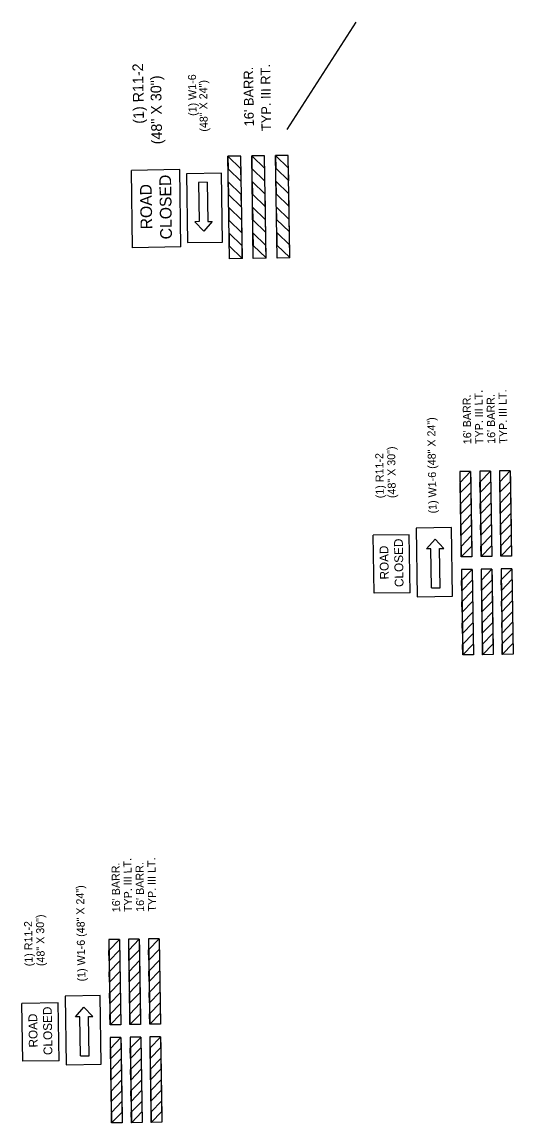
# Model space of a CAD drawing. Extents: x 1770018 to 1773492, y 718230 to 729141.
# Drawn here: x 1773099 to 1773468, y 718477 to 719302 of the extents above; entities that cross this region are included whole.
import ezdxf

# ---------------------------------------------------------------- set-up
doc = ezdxf.new("R2010")
doc.units = 0
doc.layers.add('R_Border PE', color=7, linetype='Continuous')
doc.layers.add('R_MOT', color=7, linetype='Continuous')

msp = doc.modelspace()

# ---------------------------------------------------------------- linework, layer by layer
at = {"layer": 'R_Border PE'}
msp.add_line((1773298.17, 719221.46), (1773350.06, 719301.98), dxfattribs=at)
at = {"layer": 'R_MOT'}
for p, q in [((1773263.38, 719201.45), (1773253.73, 719201.3)), ((1773254.92, 719124.43), (1773253.73, 719201.3)), ((1773263.36, 719201.39), (1773263.3, 719201.45)), ((1773264.57, 719124.58), (1773263.38, 719201.45)), ((1773281.25, 719201.72), (1773271.62, 719201.58)), ((1773281.25, 719201.72), (1773271.62, 719201.58)), ((1773272.81, 719124.71), (1773271.62, 719201.58)), ((1773282.43, 719124.86), (1773281.25, 719201.72)), ((1773299.08, 719202), (1773289.46, 719201.85)), ((1773290.64, 719124.98), (1773289.46, 719201.85)), ((1773300.26, 719125.13), (1773299.08, 719202)), ((1773217.53, 719191.29), (1773181.32, 719190.73)), ((1773182.22, 719132.77), (1773181.32, 719190.73)), ((1773218.42, 719133.33), (1773217.53, 719191.29)), ((1773238.26, 719181.82), (1773231.72, 719181.72)), ((1773231.72, 719181.72), (1773232.17, 719152.33)), ((1773238.26, 719181.82), (1773238.72, 719152.43)), ((1773232.17, 719152.33), (1773228.9, 719152.28)), ((1773235.55, 719145.21), (1773228.9, 719152.28)), ((1773241.99, 719152.48), (1773235.55, 719145.21)), ((1773238.72, 719152.43), (1773241.99, 719152.48)), ((1773218.42, 719133.33), (1773182.22, 719132.77)), ((1773264.57, 719124.58), (1773254.92, 719124.43)), ((1773282.43, 719124.86), (1773272.81, 719124.71)), ((1773300.26, 719125.13), (1773290.64, 719124.98)), ((1773435.89, 718965.08), (1773427.85, 718964.95)), ((1773427.85, 718964.95), (1773428.84, 718900.93)), ((1773435.89, 718965.08), (1773436.87, 718901.05)), ((1773450.77, 718965.3), (1773442.75, 718965.18)), ((1773442.75, 718965.18), (1773443.74, 718901.16)), ((1773450.77, 718965.3), (1773451.75, 718901.28)), ((1773465.62, 718965.53), (1773457.61, 718965.41)), ((1773457.61, 718965.41), (1773458.59, 718901.39)), ((1773465.62, 718965.53), (1773466.61, 718901.51)), ((1773389.88, 718917.52), (1773362.74, 718917.11)), ((1773363.41, 718873.66), (1773362.74, 718917.11)), ((1773390.55, 718874.08), (1773389.88, 718917.52)), ((1773402.84, 718907.06), (1773409.27, 718914.33)), ((1773409.27, 718914.33), (1773415.93, 718907.26)), ((1773406.11, 718907.11), (1773402.84, 718907.06)), ((1773406.56, 718877.72), (1773406.11, 718907.11)), ((1773412.65, 718907.21), (1773415.93, 718907.26)), ((1773413.11, 718877.82), (1773412.65, 718907.21)), ((1773436.87, 718901.05), (1773428.84, 718900.93)), ((1773436.85, 718901.1), (1773436.8, 718901.05)), ((1773451.75, 718901.28), (1773443.74, 718901.16)), ((1773451.75, 718901.28), (1773443.74, 718901.16)), ((1773466.61, 718901.51), (1773458.59, 718901.39)), ((1773437.02, 718891.55), (1773428.98, 718891.43)), ((1773428.98, 718891.43), (1773429.97, 718827.41)), ((1773437.02, 718891.55), (1773438.01, 718827.53)), ((1773451.9, 718891.78), (1773443.88, 718891.66)), ((1773443.88, 718891.66), (1773444.87, 718827.63)), ((1773451.9, 718891.78), (1773452.89, 718827.76)), ((1773466.75, 718892.01), (1773458.74, 718891.89)), ((1773458.74, 718891.89), (1773459.72, 718827.86)), ((1773466.75, 718892.01), (1773467.74, 718827.99)), ((1773390.55, 718874.08), (1773363.41, 718873.66)), ((1773406.56, 718877.72), (1773413.11, 718877.82)), ((1773438.01, 718827.53), (1773429.97, 718827.41)), ((1773437.98, 718827.58), (1773437.94, 718827.53)), ((1773452.89, 718827.76), (1773444.87, 718827.63)), ((1773452.89, 718827.76), (1773444.87, 718827.63)), ((1773467.74, 718827.99), (1773459.72, 718827.86)), ((1773172.33, 718614.17), (1773164.29, 718614.05)), ((1773164.29, 718614.05), (1773165.27, 718550.03)), ((1773172.33, 718614.17), (1773173.31, 718550.15)), ((1773187.21, 718614.4), (1773179.19, 718614.28)), ((1773179.19, 718614.28), (1773180.18, 718550.26)), ((1773187.21, 718614.4), (1773188.19, 718550.38)), ((1773202.06, 718614.63), (1773194.04, 718614.51)), ((1773194.04, 718614.51), (1773195.03, 718550.48)), ((1773202.06, 718614.63), (1773203.05, 718550.61)), ((1773126.32, 718566.62), (1773099.18, 718566.21)), ((1773099.85, 718522.76), (1773099.18, 718566.21)), ((1773126.99, 718523.18), (1773126.32, 718566.62)), ((1773139.28, 718556.15), (1773145.71, 718563.43)), ((1773145.71, 718563.43), (1773152.37, 718556.36)), ((1773142.55, 718556.2), (1773139.28, 718556.15)), ((1773143, 718526.82), (1773142.55, 718556.2)), ((1773149.09, 718556.31), (1773152.37, 718556.36)), ((1773149.55, 718526.92), (1773149.09, 718556.31)), ((1773188.19, 718550.38), (1773180.18, 718550.26)), ((1773188.19, 718550.38), (1773180.18, 718550.26)), ((1773203.05, 718550.61), (1773195.03, 718550.48)), ((1773173.31, 718550.15), (1773165.27, 718550.03)), ((1773173.29, 718550.2), (1773173.24, 718550.15)), ((1773173.46, 718540.65), (1773165.42, 718540.53)), ((1773165.42, 718540.53), (1773166.41, 718476.5)), ((1773173.46, 718540.65), (1773174.45, 718476.63)), ((1773188.34, 718540.88), (1773180.32, 718540.76)), ((1773180.32, 718540.76), (1773181.31, 718476.73)), ((1773188.34, 718540.88), (1773189.32, 718476.86)), ((1773203.19, 718541.11), (1773195.18, 718540.99)), ((1773195.18, 718540.99), (1773196.16, 718476.96)), ((1773203.19, 718541.11), (1773204.18, 718477.09)), ((1773143, 718526.82), (1773149.55, 718526.92)), ((1773126.99, 718523.18), (1773099.85, 718522.76)), ((1773174.45, 718476.63), (1773166.41, 718476.5)), ((1773174.42, 718476.68), (1773174.37, 718476.63)), ((1773189.32, 718476.86), (1773181.31, 718476.73)), ((1773189.32, 718476.86), (1773181.31, 718476.73)), ((1773204.18, 718477.09), (1773196.16, 718476.96))]:
    msp.add_line(p, q, dxfattribs=at)
for points in [[(1773253.73, 719201.3), (1773253.91, 719191.85), (1773263.65, 719182.4), (1773263.5, 719191.83)], [(1773271.62, 719201.58), (1773271.8, 719192.13), (1773281.54, 719182.68), (1773281.39, 719192.1)], [(1773289.46, 719201.85), (1773289.63, 719192.4), (1773299.37, 719182.95), (1773299.23, 719192.38)], [(1773249.72, 719137.03), (1773248.93, 719188.55), (1773222.58, 719188.15), (1773223.37, 719136.62)], [(1773254.03, 719182.09), (1773254.2, 719172.64), (1773263.94, 719163.2), (1773263.8, 719172.62)], [(1773271.92, 719182.37), (1773272.09, 719172.92), (1773281.84, 719163.47), (1773281.69, 719172.89)], [(1773289.75, 719182.64), (1773289.93, 719173.19), (1773299.67, 719163.75), (1773299.52, 719173.17)], [(1773254.32, 719162.89), (1773254.5, 719153.44), (1773264.24, 719143.99), (1773264.09, 719153.41)], [(1773272.22, 719163.16), (1773272.39, 719153.71), (1773282.13, 719144.27), (1773281.99, 719153.69)], [(1773290.05, 719163.44), (1773290.22, 719153.99), (1773299.97, 719144.54), (1773299.82, 719153.96)], [(1773254.62, 719143.68), (1773254.79, 719134.23), (1773264.54, 719124.78), (1773264.39, 719134.2)], [(1773272.51, 719143.95), (1773272.69, 719134.5), (1773282.43, 719125.06), (1773282.28, 719134.48)], [(1773290.35, 719144.23), (1773290.52, 719134.78), (1773300.26, 719125.33), (1773300.12, 719134.75)], [(1773428.1, 718948.92), (1773428, 718956.79), (1773435.87, 718964.91), (1773435.99, 718957.06)], [(1773443, 718949.15), (1773442.9, 718957.02), (1773450.77, 718965.14), (1773450.89, 718957.29)], [(1773457.85, 718949.38), (1773457.76, 718957.25), (1773465.62, 718965.37), (1773465.74, 718957.52)], [(1773428.34, 718932.92), (1773428.24, 718940.79), (1773436.11, 718948.91), (1773436.23, 718941.06)], [(1773443.24, 718933.15), (1773443.15, 718941.02), (1773451.02, 718949.14), (1773451.14, 718941.29)], [(1773458.1, 718933.38), (1773458, 718941.25), (1773465.87, 718949.37), (1773465.99, 718941.52)], [(1773428.59, 718916.93), (1773428.49, 718924.8), (1773436.36, 718932.91), (1773436.48, 718925.06)], [(1773443.49, 718917.15), (1773443.39, 718925.03), (1773451.26, 718933.14), (1773451.38, 718925.29)], [(1773458.35, 718917.38), (1773458.25, 718925.26), (1773466.12, 718933.37), (1773466.24, 718925.52)], [(1773395.11, 718922.51), (1773395.9, 718870.99), (1773422.25, 718871.39), (1773421.46, 718922.92)], [(1773428.84, 718900.93), (1773428.74, 718908.8), (1773436.61, 718916.91), (1773436.73, 718909.07)], [(1773443.74, 718901.16), (1773443.64, 718909.03), (1773451.51, 718917.14), (1773451.63, 718909.3)], [(1773458.59, 718901.39), (1773458.49, 718909.26), (1773466.36, 718917.37), (1773466.48, 718909.52)], [(1773429.23, 718875.4), (1773429.13, 718883.27), (1773437, 718891.39), (1773437.12, 718883.54)], [(1773444.13, 718875.63), (1773444.03, 718883.5), (1773451.9, 718891.62), (1773452.02, 718883.77)], [(1773458.99, 718875.86), (1773458.89, 718883.73), (1773466.76, 718891.84), (1773466.88, 718884)], [(1773429.48, 718859.4), (1773429.38, 718867.27), (1773437.25, 718875.39), (1773437.37, 718867.54)], [(1773444.38, 718859.63), (1773444.28, 718867.5), (1773452.15, 718875.62), (1773452.27, 718867.77)], [(1773459.23, 718859.86), (1773459.13, 718867.73), (1773467, 718875.85), (1773467.12, 718868)], [(1773429.72, 718843.4), (1773429.62, 718851.27), (1773437.49, 718859.39), (1773437.61, 718851.54)], [(1773444.62, 718843.63), (1773444.53, 718851.5), (1773452.39, 718859.62), (1773452.52, 718851.77)], [(1773459.48, 718843.86), (1773459.38, 718851.73), (1773467.25, 718859.85), (1773467.37, 718852)], [(1773429.97, 718827.41), (1773429.87, 718835.28), (1773437.74, 718843.39), (1773437.86, 718835.54)], [(1773444.87, 718827.63), (1773444.77, 718835.51), (1773452.64, 718843.62), (1773452.76, 718835.77)], [(1773459.72, 718827.86), (1773459.63, 718835.74), (1773467.5, 718843.85), (1773467.62, 718836)], [(1773164.53, 718598.02), (1773164.44, 718605.89), (1773172.31, 718614.01), (1773172.43, 718606.16)], [(1773179.44, 718598.25), (1773179.34, 718606.12), (1773187.21, 718614.24), (1773187.33, 718606.39)], [(1773194.29, 718598.48), (1773194.19, 718606.35), (1773202.06, 718614.46), (1773202.18, 718606.62)], [(1773164.78, 718582.02), (1773164.68, 718589.89), (1773172.55, 718598.01), (1773172.67, 718590.16)], [(1773179.68, 718582.25), (1773179.59, 718590.12), (1773187.45, 718598.24), (1773187.58, 718590.39)], [(1773194.54, 718582.48), (1773194.44, 718590.35), (1773202.31, 718598.47), (1773202.43, 718590.62)], [(1773165.03, 718566.02), (1773164.93, 718573.9), (1773172.8, 718582.01), (1773172.92, 718574.16)], [(1773179.93, 718566.25), (1773179.83, 718574.13), (1773187.7, 718582.24), (1773187.82, 718574.39)], [(1773194.78, 718566.48), (1773194.69, 718574.35), (1773202.56, 718582.47), (1773202.68, 718574.62)], [(1773131.54, 718571.61), (1773132.34, 718520.09), (1773158.69, 718520.49), (1773157.89, 718572.02)], [(1773165.27, 718550.03), (1773165.18, 718557.9), (1773173.04, 718566.01), (1773173.17, 718558.16)], [(1773180.18, 718550.26), (1773180.08, 718558.13), (1773187.95, 718566.24), (1773188.07, 718558.39)], [(1773195.03, 718550.48), (1773194.93, 718558.36), (1773202.8, 718566.47), (1773202.92, 718558.62)], [(1773165.67, 718524.5), (1773165.57, 718532.37), (1773173.44, 718540.48), (1773173.56, 718532.64)], [(1773180.57, 718524.73), (1773180.47, 718532.6), (1773188.34, 718540.71), (1773188.46, 718532.87)], [(1773195.42, 718524.96), (1773195.33, 718532.83), (1773203.19, 718540.94), (1773203.32, 718533.1)], [(1773165.91, 718508.5), (1773165.82, 718516.37), (1773173.68, 718524.49), (1773173.81, 718516.64)], [(1773180.82, 718508.73), (1773180.72, 718516.6), (1773188.59, 718524.72), (1773188.71, 718516.87)], [(1773195.67, 718508.96), (1773195.57, 718516.83), (1773203.44, 718524.94), (1773203.56, 718517.1)], [(1773166.16, 718492.5), (1773166.06, 718500.37), (1773173.93, 718508.49), (1773174.05, 718500.64)], [(1773181.06, 718492.73), (1773180.97, 718500.6), (1773188.83, 718508.72), (1773188.95, 718500.87)], [(1773195.92, 718492.96), (1773195.82, 718500.83), (1773203.69, 718508.95), (1773203.81, 718501.1)], [(1773181.31, 718476.73), (1773181.21, 718484.61), (1773189.08, 718492.72), (1773189.2, 718484.87)], [(1773196.16, 718476.96), (1773196.07, 718484.83), (1773203.93, 718492.95), (1773204.06, 718485.1)], [(1773166.41, 718476.5), (1773166.31, 718484.38), (1773174.18, 718492.49), (1773174.3, 718484.64)]]:
    msp.add_lwpolyline(points, close=True, dxfattribs=at)

# ---------------------------------------------------------------- texts
for s, height, p in [('(1) R11-2', 8.004, (1773190.75, 719225.77)), ('TYP. III RT.', 7.2036, (1773286.19, 719220.25)), ('(48" X 30")', 8.004, (1773204.37, 719210.34)), ('(1) W1-6', 6, (1773230.24, 719231.62)), ("16' BARR.", 7.204, (1773273.26, 719223.79)), ('(48" X 24")', 6, (1773238.67, 719219.82)), ('CLOSED', 8.817, (1773211.79, 719139.08)), ('ROAD', 8.774, (1773196.98, 719146.63)), ("16' BARR.", 6, (1773436.46, 718985.49)), ('TYP. III LT.', 6, (1773445.46, 718985.63)), ("16' BARR.", 6, (1773454.46, 718985.77)), ('TYP. III LT.', 6, (1773463.46, 718985.91)), ('(1) W1-6 (48" X 24")', 6, (1773410.39, 718933.57)), ('(48" X 30")', 6, (1773379.81, 718945.09)), ('(1) R11-2', 6, (1773370.81, 718944.95)), ('CLOSED', 6.61, (1773385.58, 718878.39)), ('ROAD', 6.577, (1773374.48, 718884.05)), ('TYP. III LT.', 6, (1773181.9, 718634.73)), ('TYP. III LT.', 6, (1773199.9, 718635.01)), ("16' BARR.", 6, (1773172.9, 718634.59)), ("16' BARR.", 6, (1773190.9, 718634.87)), ('(1) W1-6 (48" X 24")', 6, (1773146.83, 718582.67)), ('(1) R11-2', 6, (1773107.25, 718594.05)), ('(48" X 30")', 6, (1773116.25, 718594.19)), ('CLOSED', 6.61, (1773122.02, 718527.49)), ('ROAD', 6.577, (1773110.92, 718533.15))]:
    msp.add_text(s, height=height, rotation=90.88269, dxfattribs=at).set_placement(p)

doc.saveas('drawing.dxf')
